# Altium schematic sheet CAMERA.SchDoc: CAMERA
size A4; CompanyName: Arduino srl; DrawnBy: Silvio Navaretti; DocumentNumber: ASX00039; SheetNumber: 5; SheetTotal: 8; RevAuthor: Silvio Navaretti
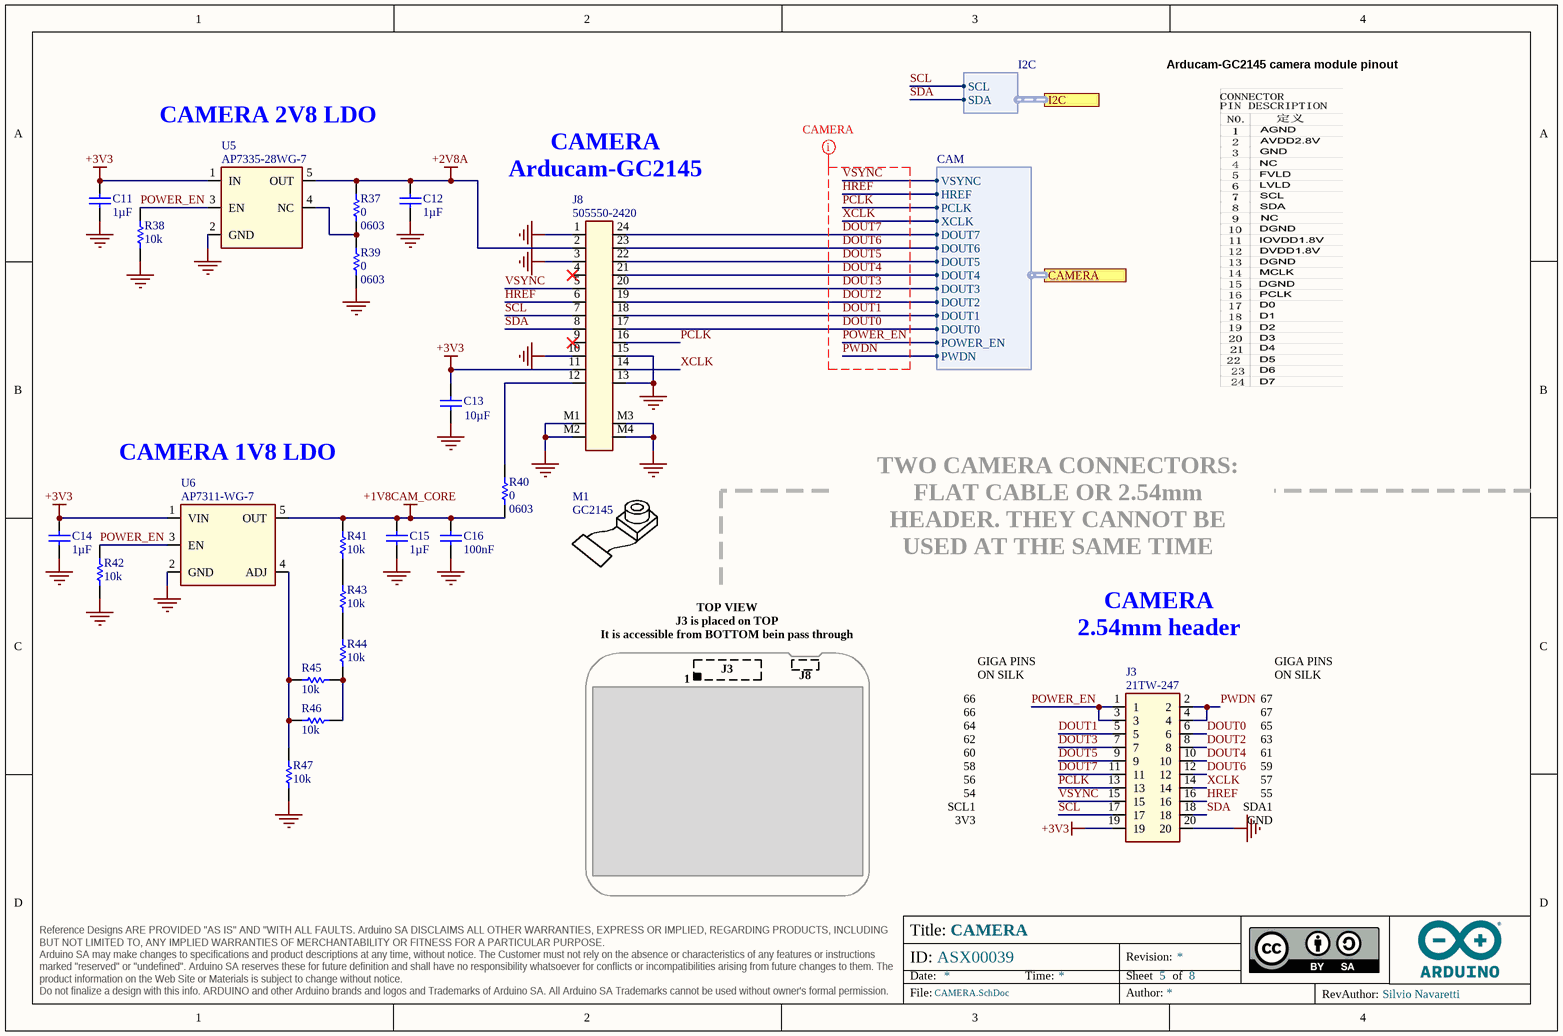
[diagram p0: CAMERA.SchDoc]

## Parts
C11  value 1µF  [CAP-0603]  (hidden comment: TMK107BJ105MAHT)
C12  value 1µF  [CAP-0603]  (hidden comment: TMK107BJ105MAHT)
C13  value 10µF  [CAP-0603]  (hidden comment: GRM188R61C106KAALD)
C14  value 1µF  [CAP-0603]  (hidden comment: TMK107BJ105MAHT)
C15  value 1µF  [CAP-0603]  (hidden comment: TMK107BJ105MAHT)
C16  value 100nF  [CAP-0603]  (hidden comment: C0603C104K5RAC3190)
J3  21TW-247  [21TW-247]
J8  505550-2420  [503772-2420-Footprint-1]
M1  GC2145  [GC2145-Footprint-1]  (no BOM)
R37  value 0  Case Code (Imperial): 0603  [RES-0603]  (hidden comment: CRCW06030000Z0EAC)
R38  value 10k  [RES-0603]  (hidden comment: CRCW060310K0JNEAC)
R39  value 0  Case Code (Imperial): 0603  [RES-0603]  (hidden comment: CRCW06030000Z0EAC)
R40  value 0  Case Code (Imperial): 0603  [RES-0603]  (hidden comment: CRCW06030000Z0EAC)
R41  value 10k  [RES-0603]  (hidden comment: CRCW060310K0JNEAC)
R42  value 10k  [RES-0603]  (hidden comment: CRCW060310K0JNEAC)
R43  value 10k  [RES-0603]  (hidden comment: CRCW060310K0JNEAC)
R44  value 10k  [RES-0603]  (hidden comment: CRCW060310K0JNEAC)
R45  value 10k  [RES-0603]  (hidden comment: CRCW060310K0JNEAC)
R46  value 10k  [RES-0603]  (hidden comment: CRCW060310K0JNEAC)
R47  value 10k  [RES-0603]  (hidden comment: CRCW060310K0JNEAC)
U5  AP7335-28WG-7  [SOT25]
U6  AP7311-WG-7  [SOT23-5]

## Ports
CAMERA (harness CAM), I2C (harness I2C)

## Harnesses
CAM: VSYNC, HREF, PCLK, XCLK, DOUT7, DOUT6, DOUT5, DOUT4, DOUT3, DOUT2, DOUT1, DOUT0, POWER_EN, PWDN
I2C: SDA, SCL

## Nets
+1V8CAM_CORE: C15.2 C16.2 R40.1 R41.2 U6.5(OUT)
+2V8A: C12.2 J8.2 R37.2 U5.5(OUT)
+3V3: C11.2 C13.2 C14.2 J3.19 J8.11 U5.1(IN) U6.1(VIN)
GND: C11.1 C12.1 C13.1 C14.1 C15.1 C16.1 J3.20 J8.1 J8.3 J8.10 J8.13 J8.15 J8.M1 J8.M2 J8.M3 J8.M4 R38.1 R39.1 R42.1 R47.1 U5.2(GND) U6.2(GND)
DOUT0: J3.6 J8.17 ; port CAMERA.DOUT0
DOUT1: J3.5 J8.18 ; port CAMERA.DOUT1
DOUT2: J3.8 J8.19 ; port CAMERA.DOUT2
DOUT3: J3.7 J8.20 ; port CAMERA.DOUT3
DOUT4: J3.10 J8.21 ; port CAMERA.DOUT4
DOUT5: J3.9 J8.22 ; port CAMERA.DOUT5
DOUT6: J3.12 J8.23 ; port CAMERA.DOUT6
DOUT7: J3.11 J8.24 ; port CAMERA.DOUT7
HREF: J3.16 J8.6 ; port CAMERA.HREF
PCLK: J3.13 J8.16 ; port CAMERA.PCLK
POWER_EN: J3.1 J3.3 R38.2 R42.2 U5.3(EN) U6.3(EN) ; port CAMERA.POWER_EN
PWDN: J3.2 J3.4 ; port CAMERA.PWDN
SCL: J3.17 J8.7 ; port I2C.SCL
SDA: J3.18 J8.8 ; port I2C.SDA
VSYNC: J3.15 J8.5 ; port CAMERA.VSYNC
XCLK: J3.14 J8.14 ; port CAMERA.XCLK
NetJ8_12: J8.12 R40.2
NetR37_1: R37.1 R39.2 U5.4(NC)
NetR41_1: R41.1 R43.2
NetR43_1: R43.1 R44.2
NetR44_1: R44.1 R45.1 R46.1
NetR45_2: R45.2 R46.2 R47.2 U6.4(ADJ)

Not connected (* = marked no-connect by the designer): J8 4* 9*

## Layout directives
net class CAMERA: DOUT0, DOUT1, DOUT2, DOUT3, DOUT4, DOUT5, DOUT6, DOUT7, HREF, PCLK, POWER_EN, PWDN, VSYNC, XCLK

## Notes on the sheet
- Arducam-GC2145 camera module pinout
- CAMERA 2V8 LDO
- CAMERA
  Arducam-GC2145
- CAMERA 1V8 LDO
- TWO CAMERA CONNECTORS: FLAT CABLE OR 2.54mm HEADER. THEY CANNOT BE USED AT THE SAME TIME
- TOP VIEW
  J3 is placed on TOP
  It is accessible from BOTTOM bein pass through
- CAMERA
  2.54mm header
- 1
- J3
- J8
- 66
- GIGA PINS ON SILK
- 67
- 64
- 62
- 60
- 58
- 56
- 65
- 63
- 61
- 59
- 57
- 54
- SCL1
- 3V3
- 55
- SDA1
- GND

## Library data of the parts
C11 C12 C14 C15 = C0077-A.10: CAP CHIP 0603 1UF 25V X5R 20%; Manufacturer: Taiyo Yuden; Code Arduino: C0077
C13 = C0071-A.9: CAP CHIP 0603 10uF 16V X5R 10%; Manufacturer: Murata; Code Arduino: C0071
C16 = C0043-A.11: CAP CHIP 0603 100nF 50V X7R 10%; Manufacturer: KEMET; Code Arduino: 0015
J3 = J0249-A.9: CONN SOCKET 2ROW 20POS VERTICAL PASS THROUGH + SMD with fixing + pick and place cap, in reel; Manufacturer: 4UCON; Connector Type: BOARD CONNECTOR; Code Arduino: J0249; Number of Contacts: 20
J8 = J0079-A.8: CONN RCPT 24POS SMD GOLD; Manufacturer: Molex; Code Arduino: J0079
M1 = M0018-A.2: MODULE CAMERA ARDUCAM-GC2145; Code Arduino: M0018
R37 R39 R40 = R0096-A.13: RES CHIP 0603 0R 1/10W; Manufacturer: Vishay; Power: 100mW; Tolerance: J; Code Arduino: 0233
R38 R41-R47 = R0090-A.13: RES CHIP 0603 10k 5% 1/10W B.5k; Manufacturer: Vishay; Code Arduino: 0028; Power: 100mW
U5 = U0109-A.7: IC V-REG LDO 2.8V 300mA  SOT25; Manufacturer: Diodes Inc; Min Current Limit: 400mA; Number of Regulators: 1; Dropout Voltage: 150mV; Min Input Voltage: 2V; Max Input Voltage: 6V; Polarity: Positive; Accuracy: 2%; Code Arduino: U0109; Quiescent Current: 35uA; Output Type: Fixed
U6 = U0220-A.3: IC LDO ADJ 0.8V Min, 5V Max, 0.3V Dropout PDSO5; Manufacturer: Diodes Incorporated; Code Arduino: U0220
